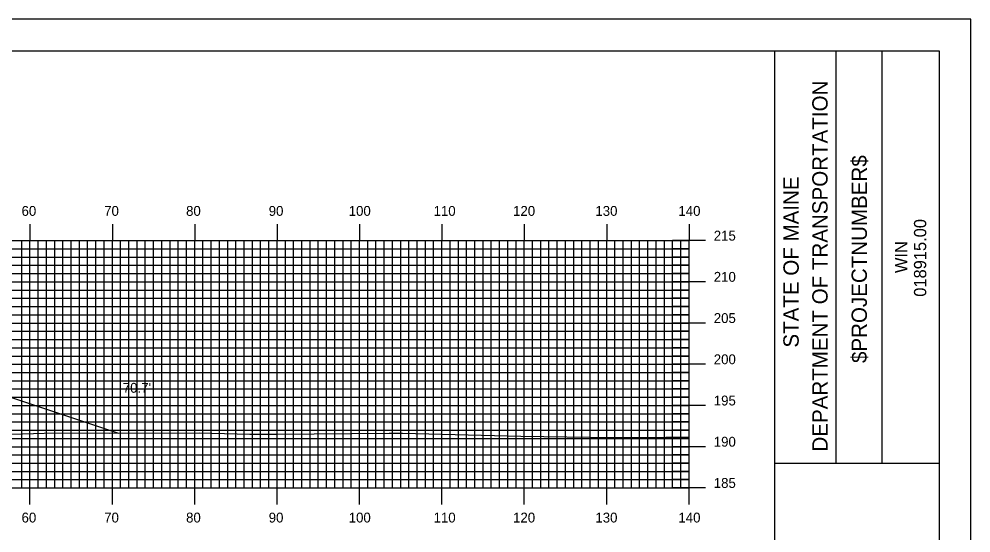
# Model space of a CAD drawing. Extents: x 1815309 to 1815652, y 442591 to 442811.
# Drawn here: x 1815533.2 to 1815648.7, y 442748.2 to 442810.5 of the extents above; entities that cross this region are included whole.
import ezdxf

# ---------------------------------------------------------------- set-up
doc = ezdxf.new("R2010")
doc.units = 0
for name, color, linetype in [('BORDER', 7, 'Continuous'), ('D_Roadway_Centerline', 7, 'Continuous'), ('D_Roadway_SlopeLines', 7, 'Continuous'), ('D_Text_Standard', 7, 'Continuous'), ('H_V ANNOTATION', 7, 'Continuous'), ('MAJOR', 7, 'Continuous'), ('MINOR', 7, 'Continuous'), ('PLOT BOUNDARY', 7, 'Continuous'), ('S_Roadway_Centerline', 7, 'Continuous')]:
    doc.layers.add(name, color=color, linetype=linetype)

msp = doc.modelspace()

# ---------------------------------------------------------------- linework, layer by layer
at = {"layer": 'BORDER'}
for p, q in [((1815624.93, 442596.67), (1815624.93, 442806.67)), ((1815632.39, 442756.66), (1815632.39, 442806.66)), ((1815637.98, 442756.66), (1815637.98, 442806.66)), ((1815624.94, 442756.65), (1815644.93, 442756.65))]:
    msp.add_line(p, q, dxfattribs=at)
msp.add_lwpolyline([(1815324.93, 442596.67), (1815644.93, 442596.67), (1815644.93, 442806.67), (1815324.93, 442806.67)], close=True, dxfattribs=at)
at = {"layer": 'D_Roadway_Centerline'}
msp.add_lwpolyline([(1815411.13, 442762.8), (1815442.53, 442773.27), (1815444.36, 442773.73), (1815454.53, 442776.27), (1815462.53, 442776.59), (1815474.53, 442776.77), (1815486.53, 442776.53), (1815494.53, 442776.21), (1815504.71, 442773.67), (1815506.53, 442773.21), (1815545.26, 442760.3)], dxfattribs=at)
at = {"layer": 'D_Roadway_SlopeLines'}
msp.add_lwpolyline([(1815494.53, 442776.21), (1815506.53, 442773.21), (1815545.26, 442760.3)], dxfattribs=at)
at = {"layer": 'MAJOR'}
for p, q in [((1815534.53, 442785.67), (1815534.53, 442783.67)), ((1815544.53, 442785.67), (1815544.53, 442783.67)), ((1815554.53, 442785.67), (1815554.53, 442783.67)), ((1815564.53, 442785.67), (1815564.53, 442783.67)), ((1815574.53, 442785.67), (1815574.53, 442783.67)), ((1815584.53, 442785.67), (1815584.53, 442783.67)), ((1815594.53, 442785.67), (1815594.53, 442783.67)), ((1815604.53, 442785.67), (1815604.53, 442783.67)), ((1815614.53, 442785.67), (1815614.53, 442783.67)), ((1815334.53, 442783.67), (1815614.53, 442783.67)), ((1815334.53, 442783.67), (1815614.53, 442783.67)), ((1815534.53, 442753.67), (1815534.53, 442783.67)), ((1815544.53, 442753.67), (1815544.53, 442783.67)), ((1815554.53, 442753.67), (1815554.53, 442783.67)), ((1815564.53, 442753.67), (1815564.53, 442783.67)), ((1815574.53, 442753.67), (1815574.53, 442783.67)), ((1815584.53, 442753.67), (1815584.53, 442783.67)), ((1815594.53, 442753.67), (1815594.53, 442783.67)), ((1815604.53, 442753.67), (1815604.53, 442783.67)), ((1815616.54, 442783.67), (1815612.53, 442783.67)), ((1815614.53, 442753.67), (1815614.53, 442783.67)), ((1815614.53, 442753.67), (1815614.53, 442783.67)), ((1815334.53, 442778.67), (1815614.53, 442778.67)), ((1815616.54, 442778.67), (1815612.53, 442778.67)), ((1815334.53, 442773.67), (1815614.53, 442773.67)), ((1815616.54, 442773.67), (1815612.53, 442773.67)), ((1815334.53, 442768.67), (1815614.53, 442768.67)), ((1815616.54, 442768.67), (1815612.53, 442768.67)), ((1815334.53, 442763.67), (1815614.53, 442763.67)), ((1815616.54, 442763.67), (1815612.53, 442763.67)), ((1815334.53, 442758.67), (1815614.53, 442758.67)), ((1815616.54, 442758.67), (1815612.53, 442758.67)), ((1815334.53, 442753.67), (1815614.53, 442753.67)), ((1815334.53, 442753.67), (1815614.53, 442753.67)), ((1815534.53, 442751.66), (1815534.53, 442753.67)), ((1815544.53, 442751.66), (1815544.53, 442753.67)), ((1815554.53, 442751.66), (1815554.53, 442753.67)), ((1815564.53, 442751.66), (1815564.53, 442753.67)), ((1815574.53, 442751.66), (1815574.53, 442753.67)), ((1815584.53, 442751.66), (1815584.53, 442753.67)), ((1815594.53, 442751.66), (1815594.53, 442753.67)), ((1815604.53, 442751.66), (1815604.53, 442753.67)), ((1815616.54, 442753.67), (1815612.53, 442753.67)), ((1815614.53, 442751.66), (1815614.53, 442753.67))]:
    msp.add_line(p, q, dxfattribs=at)
at = {"layer": 'MINOR'}
for p, q in [((1815533.53, 442753.67), (1815533.53, 442783.67)), ((1815535.53, 442753.67), (1815535.53, 442783.67)), ((1815536.53, 442753.67), (1815536.53, 442783.67)), ((1815537.53, 442753.67), (1815537.53, 442783.67)), ((1815538.53, 442753.67), (1815538.53, 442783.67)), ((1815539.53, 442753.67), (1815539.53, 442783.67)), ((1815540.53, 442753.67), (1815540.53, 442783.67)), ((1815541.53, 442753.67), (1815541.53, 442783.67)), ((1815542.53, 442753.67), (1815542.53, 442783.67)), ((1815543.53, 442753.67), (1815543.53, 442783.67)), ((1815545.53, 442753.67), (1815545.53, 442783.67)), ((1815546.53, 442753.67), (1815546.53, 442783.67)), ((1815547.53, 442753.67), (1815547.53, 442783.67)), ((1815548.53, 442753.67), (1815548.53, 442783.67)), ((1815549.53, 442753.67), (1815549.53, 442783.67)), ((1815550.53, 442753.67), (1815550.53, 442783.67)), ((1815551.53, 442753.67), (1815551.53, 442783.67)), ((1815552.53, 442753.67), (1815552.53, 442783.67)), ((1815553.53, 442753.67), (1815553.53, 442783.67)), ((1815555.53, 442753.67), (1815555.53, 442783.67)), ((1815556.53, 442753.67), (1815556.53, 442783.67)), ((1815557.53, 442753.67), (1815557.53, 442783.67)), ((1815558.53, 442753.67), (1815558.53, 442783.67)), ((1815559.53, 442753.67), (1815559.53, 442783.67)), ((1815560.53, 442753.67), (1815560.53, 442783.67)), ((1815561.53, 442753.67), (1815561.53, 442783.67)), ((1815562.53, 442753.67), (1815562.53, 442783.67)), ((1815563.53, 442753.67), (1815563.53, 442783.67)), ((1815565.53, 442753.67), (1815565.53, 442783.67)), ((1815566.53, 442753.67), (1815566.53, 442783.67)), ((1815567.53, 442753.67), (1815567.53, 442783.67)), ((1815568.53, 442753.67), (1815568.53, 442783.67)), ((1815569.53, 442753.67), (1815569.53, 442783.67)), ((1815570.53, 442753.67), (1815570.53, 442783.67)), ((1815571.53, 442753.67), (1815571.53, 442783.67)), ((1815572.53, 442753.67), (1815572.53, 442783.67)), ((1815573.53, 442753.67), (1815573.53, 442783.67)), ((1815575.53, 442753.67), (1815575.53, 442783.67)), ((1815576.53, 442753.67), (1815576.53, 442783.67)), ((1815577.53, 442753.67), (1815577.53, 442783.67)), ((1815578.53, 442753.67), (1815578.53, 442783.67)), ((1815579.53, 442753.67), (1815579.53, 442783.67)), ((1815580.53, 442753.67), (1815580.53, 442783.67)), ((1815581.53, 442753.67), (1815581.53, 442783.67)), ((1815582.53, 442753.67), (1815582.53, 442783.67)), ((1815583.53, 442753.67), (1815583.53, 442783.67)), ((1815585.53, 442753.67), (1815585.53, 442783.67)), ((1815586.53, 442753.67), (1815586.53, 442783.67)), ((1815587.53, 442753.67), (1815587.53, 442783.67)), ((1815588.53, 442753.67), (1815588.53, 442783.67)), ((1815589.53, 442753.67), (1815589.53, 442783.67)), ((1815590.53, 442753.67), (1815590.53, 442783.67)), ((1815591.53, 442753.67), (1815591.53, 442783.67)), ((1815592.53, 442753.67), (1815592.53, 442783.67)), ((1815593.53, 442753.67), (1815593.53, 442783.67)), ((1815595.53, 442753.67), (1815595.53, 442783.67)), ((1815596.53, 442753.67), (1815596.53, 442783.67)), ((1815597.53, 442753.67), (1815597.53, 442783.67)), ((1815598.53, 442753.67), (1815598.53, 442783.67)), ((1815599.53, 442753.67), (1815599.53, 442783.67)), ((1815600.53, 442753.67), (1815600.53, 442783.67)), ((1815601.53, 442753.67), (1815601.53, 442783.67)), ((1815602.53, 442753.67), (1815602.53, 442783.67)), ((1815603.53, 442753.67), (1815603.53, 442783.67)), ((1815605.53, 442753.67), (1815605.53, 442783.67)), ((1815606.53, 442753.67), (1815606.53, 442783.67)), ((1815607.53, 442753.67), (1815607.53, 442783.67)), ((1815608.53, 442753.67), (1815608.53, 442783.67)), ((1815609.53, 442753.67), (1815609.53, 442783.67)), ((1815610.53, 442753.67), (1815610.53, 442783.67)), ((1815611.53, 442753.67), (1815611.53, 442783.67)), ((1815612.53, 442753.67), (1815612.53, 442783.67)), ((1815613.53, 442753.67), (1815613.53, 442783.67)), ((1815334.53, 442782.67), (1815614.53, 442782.67)), ((1815334.53, 442781.67), (1815614.53, 442781.67)), ((1815614.53, 442782.67), (1815612.53, 442782.67)), ((1815614.53, 442781.67), (1815612.53, 442781.67)), ((1815334.53, 442780.67), (1815614.53, 442780.67)), ((1815614.53, 442780.67), (1815612.53, 442780.67)), ((1815334.53, 442779.67), (1815614.53, 442779.67)), ((1815614.53, 442779.67), (1815612.53, 442779.67)), ((1815334.53, 442777.67), (1815614.53, 442777.67)), ((1815614.53, 442777.67), (1815612.53, 442777.67)), ((1815334.53, 442776.67), (1815614.53, 442776.67)), ((1815614.53, 442776.67), (1815612.53, 442776.67)), ((1815334.53, 442775.67), (1815614.53, 442775.67)), ((1815614.53, 442775.67), (1815612.53, 442775.67)), ((1815334.53, 442774.67), (1815614.53, 442774.67)), ((1815614.53, 442774.67), (1815612.53, 442774.67)), ((1815334.53, 442772.67), (1815614.53, 442772.67)), ((1815614.53, 442772.67), (1815612.53, 442772.67)), ((1815334.53, 442771.67), (1815614.53, 442771.67)), ((1815614.53, 442771.67), (1815612.53, 442771.67)), ((1815334.53, 442770.67), (1815614.53, 442770.67)), ((1815614.53, 442770.67), (1815612.53, 442770.67)), ((1815334.53, 442769.67), (1815614.53, 442769.67)), ((1815614.53, 442769.67), (1815612.53, 442769.67)), ((1815334.53, 442767.67), (1815614.53, 442767.67)), ((1815334.53, 442766.67), (1815614.53, 442766.67)), ((1815614.53, 442767.67), (1815612.53, 442767.67)), ((1815614.53, 442766.67), (1815612.53, 442766.67)), ((1815334.53, 442765.67), (1815614.53, 442765.67)), ((1815614.53, 442765.67), (1815612.53, 442765.67)), ((1815334.53, 442764.67), (1815614.53, 442764.67)), ((1815614.53, 442764.67), (1815612.53, 442764.67)), ((1815334.53, 442762.67), (1815614.53, 442762.67)), ((1815614.53, 442762.67), (1815612.53, 442762.67)), ((1815334.53, 442761.67), (1815614.53, 442761.67)), ((1815614.53, 442761.67), (1815612.53, 442761.67)), ((1815334.53, 442760.67), (1815614.53, 442760.67)), ((1815614.53, 442760.67), (1815612.53, 442760.67)), ((1815334.53, 442759.67), (1815614.53, 442759.67)), ((1815614.53, 442759.67), (1815612.53, 442759.67)), ((1815334.53, 442757.67), (1815614.53, 442757.67)), ((1815614.53, 442757.67), (1815612.53, 442757.67)), ((1815334.53, 442756.67), (1815614.53, 442756.67)), ((1815614.53, 442756.67), (1815612.53, 442756.67)), ((1815334.53, 442755.67), (1815614.53, 442755.67)), ((1815614.53, 442755.67), (1815612.53, 442755.67)), ((1815334.53, 442754.67), (1815614.53, 442754.67)), ((1815614.53, 442754.67), (1815612.53, 442754.67))]:
    msp.add_line(p, q, dxfattribs=at)
at = {"layer": 'PLOT BOUNDARY'}
msp.add_lwpolyline([(1815308.75, 442590.55), (1815648.75, 442590.55), (1815648.75, 442810.55), (1815308.75, 442810.55)], close=True, dxfattribs=at)
at = {"layer": 'S_Roadway_Centerline'}
msp.add_lwpolyline([(1815526.98, 442760.01), (1815537.6, 442760.33), (1815544.19, 442760.3), (1815555.07, 442760.33), (1815561.22, 442760.2), (1815564.48, 442760.18), (1815578.15, 442760.3), (1815579.37, 442760.29), (1815579.74, 442760.3), (1815594.13, 442759.96), (1815605.27, 442759.78), (1815611.72, 442759.82), (1815614.53, 442759.84)], dxfattribs=at)

# ---------------------------------------------------------------- texts
at = {"layer": 'BORDER'}
for s, height, p in [('DEPARTMENT OF TRANSPORTATION', 1.8635, (1815631.35, 442758.08)), ('$PROJECTNUMBER$', 1.8635, (1815636.12, 442768.82)), ('STATE OF MAINE', 1.8635, (1815627.84, 442770.69)), ('018915.00', 1.491, (1815643.32, 442776.86)), ('WIN', 1.491, (1815641.01, 442779.73))]:
    msp.add_text(s, height=height, rotation=90, dxfattribs=at).set_placement(p)
at = {"layer": 'D_Text_Standard'}
msp.add_text("70.7'", height=1.2, dxfattribs=at).set_placement((1815545.8, 442765.21))
at = {"layer": 'H_V ANNOTATION'}
for s, p in [('60', (1815533.51, 442786.67)), ('70', (1815543.54, 442786.67)), ('80', (1815553.48, 442786.67)), ('90', (1815563.51, 442786.67)), ('100', (1815573.22, 442786.67)), ('110', (1815583.52, 442786.67)), ('120', (1815593.17, 442786.67)), ('130', (1815603.16, 442786.67)), ('140', (1815613.24, 442786.67)), ('215', (1815617.53, 442783.67)), ('210', (1815617.53, 442778.67)), ('205', (1815617.53, 442773.67)), ('200', (1815617.53, 442768.67)), ('195', (1815617.53, 442763.67)), ('190', (1815617.53, 442758.67)), ('185', (1815617.53, 442753.67)), ('60', (1815533.51, 442749.47)), ('70', (1815543.54, 442749.47)), ('80', (1815553.48, 442749.47)), ('90', (1815563.51, 442749.47)), ('100', (1815573.22, 442749.47)), ('110', (1815583.52, 442749.47)), ('120', (1815593.17, 442749.47)), ('130', (1815603.16, 442749.47)), ('140', (1815613.24, 442749.47))]:
    msp.add_text(s, height=1.2, dxfattribs=at).set_placement(p)

doc.saveas('drawing.dxf')
